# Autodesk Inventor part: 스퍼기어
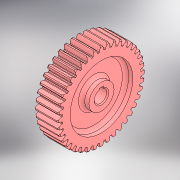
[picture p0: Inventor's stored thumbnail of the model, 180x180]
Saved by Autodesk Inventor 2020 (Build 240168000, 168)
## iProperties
Created: 2024-11
Part Number: 스퍼기어
Material: 강철, 탄소
Document SubType Name: Modeling
Designer: 1강의실14
Density: 7.85 g/cm^3
Appearance: 기본값
Author: jhkim
Sending System: Autodesk Inventor 2025
Preprocessor: ST-DEVELOPER v20
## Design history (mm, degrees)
feature "솔리드1"
node "솔리드2"
